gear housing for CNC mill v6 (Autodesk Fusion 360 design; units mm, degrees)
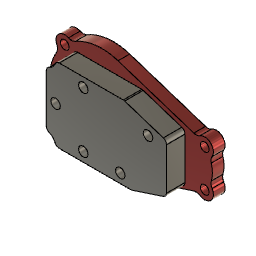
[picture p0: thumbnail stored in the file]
description: Gear Housing Assembly
derived_base_feature "Derived Base Feature1"
derived_base_feature "Derived Base Feature1" bodies "Front Housing"
derived_base_feature "Derived Base Feature1" bodies "Front Cover"
derived_base_feature "Derived Base Feature1" bodies "Back Housing"
as_built_joint "As-built1"
offset_faces "OffsetFaces1" distance 5
delete_face "DeleteFace1"
delete_face "DeleteFace2"
sketch "Sketch1" plane through (0, -21, 0) normal (0, -1, 0) x axis (1, 0, 0)
  line L1 (11.1724, 34.2225) -> (63.2283, 17.2281)
  line L2 (63.2283, -17.2281) -> (11.1724, -34.2225)
  arc A1 centre (64.7801, 21.9812) radius 5 clockwise from (67.4836, 17.7752) to (63.2283, 17.2281)
  arc A2 centre (0, 0) radius 36 clockwise from (-18.189, 31.067) to (11.1724, 34.2225)
  arc A3 centre (-20.7152, 35.3819) radius 5 clockwise from (-18.189, 31.067) to (-22.8701, 30.8701)
  arc A4 centre (-25.4558, 25.4558) radius 6 clockwise from (-30.8701, 22.8701) to (-22.8701, 30.8701)
  arc A5 centre (-35.3819, 20.7152) radius 5 clockwise from (-30.8701, 22.8701) to (-31.067, 18.189)
  arc A6 centre (0, 0) radius 36 clockwise from (-31.067, -18.189) to (-31.067, 18.189)
  arc A7 centre (-35.3819, -20.7152) radius 5 clockwise from (-31.067, -18.189) to (-30.8701, -22.8701)
  arc A8 centre (-25.4558, -25.4558) radius 6 clockwise from (-22.8701, -30.8701) to (-30.8701, -22.8701)
  arc A9 centre (-20.7152, -35.3819) radius 5 clockwise from (-22.8701, -30.8701) to (-18.189, -31.067)
  arc A10 centre (0, 0) radius 36 clockwise from (11.1724, -34.2225) to (-18.189, -31.067)
  arc A11 centre (64.7801, -21.9812) radius 5 clockwise from (63.2283, -17.2281) to (67.4836, -17.7752)
  arc A12 centre (70.7279, -12.7279) radius 6 clockwise from (75.774, -9.4818) to (67.4836, -17.7752)
  arc A13 centre (79.979, -6.7767) radius 5 clockwise from (75.774, -9.4818) to (75.201, -5.3035)
  arc A14 centre (58, 0) radius 18 clockwise from (75.201, 5.3035) to (75.201, -5.3035)
  arc A15 centre (79.979, 6.7767) radius 5 clockwise from (75.201, 5.3035) to (75.774, 9.4818)
  arc A16 centre (70.7279, 12.7279) radius 6 clockwise from (67.4836, 17.7752) to (75.774, 9.4818)
  circle C1 centre (70.7279, -12.7279) radius 3
  circle C2 centre (70.7279, 12.7279) radius 3
  circle C3 centre (-25.4558, -25.4558) radius 3
  circle C4 centre (-25.4558, 25.4558) radius 3
  circle C5 centre (0, 0) radius 5.25
  circle C6 centre (0, 0) radius 19.05
  point P1 (0, 0)
  point P34 (0, 0)
  point P35 (0, -19.05)
  point P36 (-19.05, 0)
  point P37 (0, 19.05)
  point P38 (44.45, 12.7)
  point P39 (25.4, -19.05)
  coincident P1 P34
  coincident C6 P35
  coincident C6 P36
  coincident C6 P37
  vertical P34 P35
  horizontal P1 P36
  vertical P1 P37
  dimension "d2" diameter C6 = 38.1
  dimension "d3" distance P1 P38 = 44.45
  dimension "d4" distance P1 P38 = 12.7
  dimension "d5" distance P34 P39 = 25.4
  dimension "d6" distance P34 P39 = 19.05
hole "Hole1" HoleDepth 5.715 HoleDiameter 5.1308 TipAngle 118
ground "Ground1"
ground "Ground2"
ground "Ground3"
ground "Ground4"
position "Position1"
sketch "Sketch1" plane through (0, 0, 0) normal (0, 1, 0) x axis (1, 0, 0)
  line L1 (57.15, -25.4) -> (-25.4, -25.4)
  line L2 (57.15, 25.4) -> (57.15, -25.4)
  line L3 (-25.4, 25.4) -> (57.15, 25.4)
  line L4 (-25.4, -25.4) -> (-25.4, 25.4)
  line L5 (11.1724, -34.2225) -> (63.2283, -17.2281)
  line L6 (63.2283, 17.2281) -> (11.1724, 34.2225)
  line L7 (10.1871, -31.2042) -> (62.243, -14.2098)
  line L8 (62.7357, 15.719) -> (10.6797, 32.7134)
  circle C1 centre (-25.4558, -25.4558) radius 3
  circle C2 centre (-25.4558, 25.4558) radius 3
  circle C3 centre (-25.4558, -25.4558) radius 6.35
  circle C4 centre (-25.4558, 25.4558) radius 6.35
  point P1 (0, 0)
  horizontal L1
  vertical L2
  horizontal L3
  vertical L4
  concentric C1 C3
  concentric C2 C4
  equal C3 C4
  dimension "d10" distance P1 L1 = 25.4
  dimension "d11" distance P1 L3 = 25.4 (= "d10")
  dimension "d12" distance P1 L2 = 57.15
  dimension "d13" distance P1 L4 = 25.4
  dimension "d14" diameter C3 = 12.7
  dimension "d15" = 3.175
  dimension "d16" = 1.5875
extrude "Extrude1" new body sketch "Sketch1" profile of L1 L2 L3 L4 C3 C4 L7 L8 against normal blind 12.7
fillet "Fillet1" radius 3.175
hole "Hole1" HoleDepth 12.7 HoleDiameter 6.477 TipAngle 118
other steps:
thread "Thread1"
create_component "CreateComponent1"
create_component "CreateComponent5"
create_component "CreateComponent1"
create_component "CreateComponent2"
create_component "CreateComponent3"
named bodies: "Back Housing", "Front Cover", "Front Housing"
